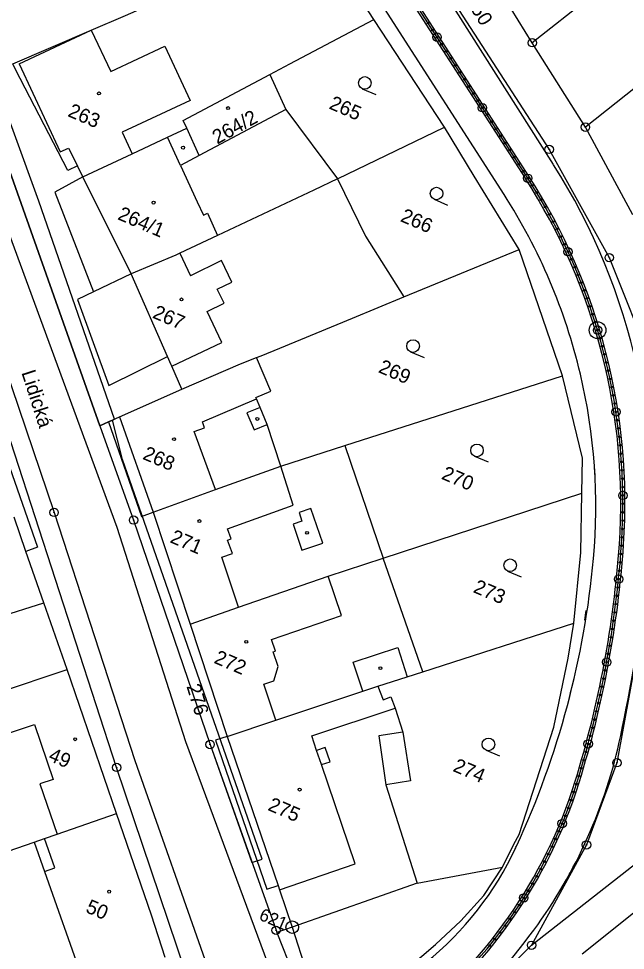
# Model space of a CAD drawing. Extents: x -548552 to -543113, y -1131925 to -1123599.
# Drawn here: x -548049 to -547976.7, y -1130669.2 to -1130558.1 of the extents above; entities that cross this region are included whole.
import ezdxf

# ---------------------------------------------------------------- set-up
doc = ezdxf.new("R2010")
doc.units = 0
for name, color, linetype in [('Hranice parcel', 7, 'Continuous'), ('Parcelní čísla', 7, 'Continuous'), ('Pop  PČ popisy', 7, 'Continuous'), ('PROFILY NÁVRH', 7, 'Continuous'), ('STANIČENÍ', 7, 'Continuous'), ('Vnitřní kresba', 7, 'Continuous'), ('Věcná břemena k části', 7, 'Continuous'), ('Značky bodu BP', 7, 'Continuous'), ('Značky budov', 7, 'Continuous'), ('Značky kultur', 7, 'Continuous')]:
    doc.layers.add(name, color=color, linetype=linetype)

msp = doc.modelspace()

# ---------------------------------------------------------------- linework, layer by layer
at = {"layer": 'Hranice parcel'}
for p, q in [((-547925.24, -1130511.69), (-547987.79, -1130560.98)), ((-547921.06, -1130523.02), (-547981.46, -1130571.05)), ((-548006.7, -1130558.22), (-548013.84, -1130547.08)), ((-547987.79, -1130560.98), (-547994.18, -1130550.73)), ((-547998.28, -1130571.06), (-548006.7, -1130558.22)), ((-548049.72, -1130563.51), (-548040.37, -1130559.48)), ((-547981.46, -1130571.05), (-547987.79, -1130560.98)), ((-548019.09, -1130564.77), (-548017.16, -1130568.93)), ((-548017.16, -1130568.93), (-548011.01, -1130577.22)), ((-548011.01, -1130577.22), (-547998.28, -1130571.06)), ((-547975.81, -1130581.5), (-547981.46, -1130571.05)), ((-548035.51, -1130574.21), (-548031.29, -1130572.24)), ((-548041.37, -1130576.96), (-548035.51, -1130574.21)), ((-548035.62, -1130588.52), (-548041.37, -1130576.96)), ((-548003.12, -1130591.29), (-547989.35, -1130585.62)), ((-547984.21, -1130600.71), (-547989.35, -1130585.62)), ((-548010.16, -1130609.02), (-547984.21, -1130600.71)), ((-548037, -1130605.6), (-548029.58, -1130602.3)), ((-548037, -1130605.6), (-548032.98, -1130616.96)), ((-548017.78, -1130611.46), (-548010.16, -1130609.02)), ((-548010.16, -1130609.02), (-548005.59, -1130622.46)), ((-548005.59, -1130622.46), (-547981.89, -1130614.69)), ((-548032.98, -1130616.96), (-548028.57, -1130630.3)), ((-548000.83, -1130635.98), (-548005.59, -1130622.46)), ((-548028.57, -1130630.3), (-548024.17, -1130643.69)), ((-548000.83, -1130635.98), (-547982.83, -1130630.21)), ((-548053.37, -1130639.11), (-548043.27, -1130635.7)), ((-548037.36, -1130652.87), (-548043.27, -1130635.7)), ((-547987.88, -1130668.6), (-547967.94, -1130652.95)), ((-547965.22, -1130656.32), (-547981.83, -1130669.68)), ((-548016.41, -1130666.44), (-548012.24, -1130679.44)), ((-547987.88, -1130668.6), (-548006.97, -1130687.25))]:
    msp.add_line(p, q, dxfattribs=at)
for points in [[(-548041.48, -1130484.13), (-548021.99, -1130517.74), (-547985.78, -1130573.7), (-547978.62, -1130586.61), (-547973.44, -1130599.62), (-547973.28, -1130611.12), (-547973.7, -1130624.88), (-547977.7, -1130646.84), (-547981.33, -1130656.63), (-547987.88, -1130668.6)], [(-548039.34, -1130606.65), (-548051.27, -1130573.08), (-548067.49, -1130533.25), (-548072.39, -1130522.4)], [(-548024.97, -1130684.14), (-548037.35, -1130647.39), (-548054.37, -1130595.1), (-548067.35, -1130560.8), (-548076.02, -1130541.68), (-548076.18, -1130541.3)], [(-548040.37, -1130559.48), (-548036.3, -1130557.72), (-548033.4, -1130556.48)], [(-548019.09, -1130564.77), (-548016.71, -1130563.5), (-548006.7, -1130558.22)], [(-548040.37, -1130559.48), (-548038.05, -1130564.43), (-548031.61, -1130561.41), (-548028.58, -1130567.87), (-548036.7, -1130571.66), (-548035.51, -1130574.21)], [(-548041.37, -1130576.96), (-548042.02, -1130575.66), (-548043.16, -1130576.23), (-548049.43, -1130564.18), (-548049.72, -1130563.51)], [(-548031.29, -1130572.24), (-548028.98, -1130571.16), (-548029.41, -1130570.24), (-548019.09, -1130564.77)], [(-548017.16, -1130568.93), (-548027.51, -1130574.43), (-548029.74, -1130575.61), (-548031.29, -1130572.24)], [(-547989.35, -1130585.62), (-547994.71, -1130576.89), (-547998.28, -1130571.06)], [(-548011.01, -1130577.22), (-548013.86, -1130578.56), (-548025.33, -1130583.96), (-548029.81, -1130586.08), (-548030.31, -1130586.31), (-548035.62, -1130588.52)], [(-548011.01, -1130577.22), (-548007.69, -1130584.04), (-548003.12, -1130591.29)], [(-548029.58, -1130602.3), (-548030.77, -1130599.56), (-548030.85, -1130599.39), (-548031.29, -1130598.38), (-548035.62, -1130588.52)], [(-548020.67, -1130598.52), (-548020.14, -1130598.3), (-548017.91, -1130597.4), (-548009.22, -1130593.81), (-548003.12, -1130591.29)], [(-548029.58, -1130602.3), (-548022.57, -1130599.28), (-548020.67, -1130598.52)], [(-548017.78, -1130611.46), (-548019.39, -1130606.5), (-548020.24, -1130604.46), (-548020.68, -1130603.46), (-548020.76, -1130603.27), (-548018.97, -1130602.52), (-548020.67, -1130598.52)], [(-547981.89, -1130614.69), (-547981.79, -1130610.5), (-547984.21, -1130600.71)], [(-548039.34, -1130606.65), (-548038.34, -1130606.19), (-548037, -1130605.6)], [(-548039.34, -1130606.65), (-548035.33, -1130617.91), (-548026.21, -1130644.66), (-548018.35, -1130666.82), (-548018.26, -1130667.08), (-548016.3, -1130672.01), (-548012.24, -1130679.44)], [(-548032.98, -1130616.96), (-548025.57, -1130614.27), (-548017.78, -1130611.46)], [(-547982.83, -1130630.21), (-547981.99, -1130621.77), (-547981.89, -1130614.69)], [(-548043.27, -1130635.7), (-548046.02, -1130627.78), (-548048.17, -1130621.63), (-548049.59, -1130617.56)], [(-548028.57, -1130630.3), (-548022.82, -1130628.3), (-548012.14, -1130624.6), (-548005.59, -1130622.46)], [(-548012.24, -1130679.44), (-548002.6, -1130671.28), (-547999.34, -1130668.52), (-547996.3, -1130665.69), (-547993.59, -1130662.67), (-547991.35, -1130659.28), (-547989.98, -1130656.53), (-547989.37, -1130655.41), (-547985.23, -1130642.61), (-547983.5, -1130634.36), (-547982.83, -1130630.21)], [(-548006.2, -1130637.71), (-548002.73, -1130636.59), (-548000.83, -1130635.98)], [(-548024.17, -1130643.69), (-548018.38, -1130641.77), (-548008.01, -1130638.31), (-548006.2, -1130637.71)], [(-548006.2, -1130637.71), (-548005.58, -1130639.33), (-548004.65, -1130638.97), (-548004.13, -1130640.33), (-548003.22, -1130643.18), (-548002.3, -1130649.01), (-548005.26, -1130649.48), (-548001.53, -1130661.2), (-548016.41, -1130666.44)], [(-548024.17, -1130643.69), (-548018.11, -1130661.46), (-548017.93, -1130662.01), (-548016.41, -1130666.44)], [(-548047.2, -1130656.29), (-548045.97, -1130655.87), (-548044.46, -1130655.34), (-548037.36, -1130652.87)], [(-548031.55, -1130670.08), (-548033.2, -1130665.02), (-548037.36, -1130652.87)], [(-548063.22, -1130661.62), (-548050.3, -1130657.38), (-548047.2, -1130656.29)], [(-548047.2, -1130656.29), (-548045.96, -1130659.81), (-548041.48, -1130672.53), (-548041.79, -1130672.64), (-548041.55, -1130673.37)]]:
    msp.add_lwpolyline(points, dxfattribs=at)
at = {"layer": 'PROFILY NÁVRH'}
msp.add_line((-547985.25, -1130575.52), (-547999.5, -1130553.08), dxfattribs=at)
for points in [[(-547988.2, -1130576.88), (-548019.2, -1130528.68), (-548034.37, -1130503.29)], [(-547988.62, -1130577.15), (-548019.63, -1130528.94), (-548034.8, -1130503.55)], [(-547991.16, -1130579.07), (-548005.43, -1130556.89)]]:
    msp.add_lwpolyline(points, dxfattribs=at)
for centre, radius, start, end in [((-548048.86, -1130615.89), 75.33, 352.3069, 32.4031), ((-548048.86, -1130615.89), 71.62, 356.0912, 32.7509), ((-548048.86, -1130615.89), 72.12, 356.0912, 32.7509), ((-548049.18, -1130616.39), 68.98, 13.3179, 32.7509), ((-548048.79, -1130616.3), 68.58, 354.8235, 13.3179), ((-548101.1, -1130612.32), 123.98, 342.7708, 356.0912), ((-548101.1, -1130612.32), 124.48, 342.7708, 356.0912), ((-548084.22, -1130613.09), 104.15, 335.2035, 354.8235), ((-548214.79, -1130593.48), 242.77, 348.0841, 352.3069), ((-548036.18, -1130631.17), 60.23, 323.7358, 348.0841), ((-548038.28, -1130631.81), 58.21, 307.0781, 342.7708), ((-548038.28, -1130631.81), 58.71, 307.0781, 342.7708), ((-548024.35, -1130640.88), 38.15, 308.652, 335.0978), ((-548051.88, -1130619.65), 79.7, 312.7399, 323.7358)]:
    msp.add_arc(centre, radius, start, end, dxfattribs=at)
at = {"layer": 'STANIČENÍ'}
msp.add_lwpolyline([(-547988.41, -1130577.01), (-548019.42, -1130528.81), (-548034.58, -1130503.42)], dxfattribs=at)
for centre, radius in [((-548000.23, -1130558.63), 0.1), ((-547999.69, -1130559.47), 0.1), ((-547999.15, -1130560.32), 0.5), ((-547999.15, -1130560.32), 0.1), ((-547998.61, -1130561.16), 0.1), ((-547998.07, -1130562), 0.1), ((-547997.53, -1130562.84), 0.1), ((-547996.99, -1130563.68), 0.1), ((-547996.44, -1130564.52), 0.1), ((-547995.9, -1130565.36), 0.1), ((-547995.36, -1130566.2), 0.1), ((-547994.82, -1130567.04), 0.1), ((-547994.28, -1130567.89), 0.1), ((-547993.74, -1130568.73), 0.5), ((-547993.74, -1130568.73), 0.1), ((-547993.2, -1130569.57), 0.1), ((-547992.66, -1130570.41), 0.1), ((-547992.12, -1130571.25), 0.1), ((-547991.58, -1130572.09), 0.1), ((-547991.03, -1130572.93), 0.1), ((-547990.49, -1130573.77), 0.1), ((-547989.95, -1130574.61), 0.1), ((-547989.41, -1130575.45), 0.1), ((-547988.87, -1130576.3), 0.1), ((-547988.33, -1130577.14), 0.5), ((-547988.33, -1130577.14), 0.1), ((-547987.8, -1130577.98), 0.1), ((-547987.27, -1130578.84), 0.1), ((-547986.77, -1130579.7), 0.1), ((-547986.27, -1130580.56), 0.1), ((-547985.78, -1130581.44), 0.1), ((-547985.31, -1130582.32), 0.1), ((-547984.85, -1130583.21), 0.1), ((-547984.4, -1130584.1), 0.1), ((-547983.96, -1130585), 0.1), ((-547983.54, -1130585.91), 0.5), ((-547983.54, -1130585.91), 0.1), ((-547983.13, -1130586.82), 0.1), ((-547982.73, -1130587.73), 0.1), ((-547982.35, -1130588.66), 0.1), ((-547981.97, -1130589.59), 0.1), ((-547981.61, -1130590.52), 0.1), ((-547981.27, -1130591.46), 0.1), ((-547980.93, -1130592.4), 0.1), ((-547980.93, -1130592.4), 0.1), ((-547980.61, -1130593.35), 0.1), ((-547980.61, -1130593.35), 0.1), ((-547980.01, -1130595.25), 1), ((-547980.31, -1130594.3), 0.1), ((-547980.31, -1130594.3), 0.1), ((-547980.01, -1130595.25), 0.5), ((-547980.01, -1130595.25), 0.5), ((-547980.01, -1130595.25), 0.1), ((-547980.01, -1130595.25), 0.1), ((-547979.73, -1130596.21), 0.1), ((-547979.73, -1130596.21), 0.1), ((-547979.46, -1130597.18), 0.1), ((-547979.46, -1130597.18), 0.1), ((-547979.21, -1130598.14), 0.1), ((-547979.21, -1130598.14), 0.1), ((-547978.97, -1130599.12), 0.1), ((-547978.97, -1130599.12), 0.1), ((-547978.74, -1130600.09), 0.1), ((-547978.74, -1130600.09), 0.1), ((-547978.53, -1130601.07), 0.1), ((-547978.53, -1130601.07), 0.1), ((-547978.33, -1130602.05), 0.1), ((-547978.15, -1130603.03), 0.1), ((-547977.81, -1130605), 0.5), ((-547977.97, -1130604.01), 0.1), ((-547977.81, -1130605), 0.1), ((-547977.67, -1130605.99), 0.1), ((-547977.54, -1130606.98), 0.1), ((-547977.42, -1130607.98), 0.1), ((-547977.32, -1130608.97), 0.1), ((-547977.23, -1130609.97), 0.1), ((-547977.15, -1130610.96), 0.1), ((-547977.09, -1130611.96), 0.1), ((-547977.04, -1130612.96), 0.1), ((-547976.99, -1130614.96), 0.5), ((-547977.01, -1130613.96), 0.1), ((-547976.99, -1130614.96), 0.1), ((-547976.98, -1130615.96), 0.1), ((-547977.01, -1130617.96), 0.1), ((-547976.99, -1130616.96), 0.1), ((-547977.05, -1130618.96), 0.1), ((-547977.1, -1130619.96), 0.1), ((-547977.16, -1130620.96), 0.1), ((-547977.24, -1130621.95), 0.1), ((-547977.32, -1130622.95), 0.1), ((-547977.51, -1130624.94), 0.5), ((-547977.41, -1130623.95), 0.1), ((-547977.51, -1130624.94), 0.1), ((-547977.72, -1130626.93), 0.1), ((-547977.61, -1130625.93), 0.1), ((-547977.85, -1130627.92), 0.1), ((-547977.98, -1130628.91), 0.1), ((-547978.11, -1130629.9), 0.1), ((-547978.26, -1130630.89), 0.1), ((-547978.41, -1130631.88), 0.1), ((-547978.57, -1130632.87), 0.1), ((-547978.92, -1130634.84), 0.5), ((-547978.74, -1130633.85), 0.1), ((-547979.11, -1130635.82), 0.1), ((-547978.92, -1130634.84), 0.1), ((-547979.3, -1130636.8), 0.1), ((-547979.5, -1130637.78), 0.1), ((-547979.71, -1130638.76), 0.1), ((-547979.92, -1130639.73), 0.1), ((-547980.15, -1130640.71), 0.1), ((-547980.38, -1130641.68), 0.1), ((-547980.62, -1130642.65), 0.1), ((-547981.13, -1130644.59), 0.5), ((-547981.13, -1130644.59), 0.1), ((-547980.87, -1130643.62), 0.1), ((-547981.39, -1130645.55), 0.1), ((-547981.66, -1130646.52), 0.1), ((-547981.94, -1130647.48), 0.1), ((-547982.23, -1130648.43), 0.1), ((-547982.52, -1130649.39), 0.1), ((-547983.16, -1130651.29), 0.1), ((-547982.83, -1130650.34), 0.1), ((-547983.5, -1130652.23), 0.1), ((-547983.85, -1130653.16), 0.1), ((-547984.23, -1130654.09), 0.5), ((-547984.23, -1130654.09), 0.1), ((-547984.62, -1130655.01), 0.1), ((-547985.44, -1130656.83), 0.1), ((-547985.02, -1130655.92), 0.1), ((-547985.88, -1130657.73), 0.1), ((-547986.33, -1130658.62), 0.1), ((-547986.79, -1130659.51), 0.1), ((-547987.77, -1130661.25), 0.1), ((-547987.28, -1130660.38), 0.1), ((-547988.28, -1130662.11), 0.1), ((-547988.81, -1130662.96), 0.5), ((-547988.81, -1130662.96), 0.1), ((-547989.9, -1130664.64), 0.1), ((-547989.35, -1130663.8), 0.1), ((-547990.47, -1130665.46), 0.1), ((-547991.05, -1130666.27), 0.1), ((-547992.26, -1130667.87), 0.1), ((-547991.65, -1130667.07), 0.1), ((-547992.88, -1130668.65), 0.1)]:
    msp.add_circle(centre, radius, dxfattribs=at)
for centre, radius, start, end in [((-548048.86, -1130615.89), 71.87, 356.0912, 32.7509), ((-548048.86, -1130615.89), 68.5, 24.3361, 25.5975), ((-548048.86, -1130615.89), 68.63, 2.1837, 3.4931), ((-548101.1, -1130612.32), 124.23, 342.7708, 356.0912), ((-548101.1, -1130612.32), 120.84, 351.6682, 352.2207), ((-548101.1, -1130612.32), 120.74, 347.0975, 347.6389), ((-548038.28, -1130631.81), 58.46, 307.0781, 342.7708), ((-548038.28, -1130631.81), 54.64, 332.4655, 333.1658), ((-548038.28, -1130631.81), 61.78, 332.5857, 332.9808)]:
    msp.add_arc(centre, radius, start, end, dxfattribs=at)
at = {"layer": 'Vnitřní kresba'}
for p, q in [((-548048.99, -1130563.51), (-548040.37, -1130559.48)), ((-548048.99, -1130563.51), (-548044.09, -1130573.99)), ((-548027.51, -1130574.43), (-548028.98, -1130571.16)), ((-548053.79, -1130574.03), (-548037.32, -1130618.76)), ((-548044.09, -1130573.99), (-548043.08, -1130573.54)), ((-548043.08, -1130573.54), (-548042.02, -1130575.66)), ((-548041.37, -1130576.96), (-548044.73, -1130578.78)), ((-548044.73, -1130578.78), (-548040.13, -1130590.67)), ((-548029.81, -1130586.08), (-548028.55, -1130588.76)), ((-548024.86, -1130586.96), (-548028.55, -1130588.76)), ((-548023.6, -1130589.54), (-548024.86, -1130586.96)), ((-548035.62, -1130588.52), (-548040.13, -1130590.67)), ((-548025.35, -1130590.38), (-548023.6, -1130589.54)), ((-548040.13, -1130590.67), (-548042.03, -1130591.58)), ((-548024.53, -1130592.02), (-548025.35, -1130590.38)), ((-548042.03, -1130591.58), (-548038.28, -1130601.87)), ((-548026.57, -1130593.01), (-548024.53, -1130592.02)), ((-548024.83, -1130596.74), (-548026.57, -1130593.01)), ((-548052.48, -1130594.39), (-548044.81, -1130616.99)), ((-548030.77, -1130599.56), (-548024.83, -1130596.74)), ((-548038.28, -1130601.87), (-548031.29, -1130598.38)), ((-548027.1, -1130606.19), (-548020.68, -1130603.46)), ((-548020.24, -1130604.46), (-548021.81, -1130605.11)), ((-548021.81, -1130605.11), (-548020.96, -1130607.14)), ((-548038.34, -1130606.19), (-548034.38, -1130617.46)), ((-548026.86, -1130606.9), (-548027.1, -1130606.19)), ((-548020.96, -1130607.14), (-548019.39, -1130606.5)), ((-548028.09, -1130607.32), (-548026.86, -1130606.9)), ((-548025.57, -1130614.27), (-548028.09, -1130607.32)), ((-548051.34, -1130608.15), (-548046.77, -1130621.14)), ((-548016.3, -1130616.13), (-548017.78, -1130611.46)), ((-548024.13, -1130618.96), (-548016.3, -1130616.13)), ((-548014.19, -1130616.51), (-548015.6, -1130616.99)), ((-548012.78, -1130620.66), (-548014.19, -1130616.51)), ((-548044.81, -1130616.99), (-548035.2, -1130646.58)), ((-548034.38, -1130617.46), (-548032.98, -1130616.96)), ((-548015.6, -1130616.99), (-548015.26, -1130618.02)), ((-548037.32, -1130618.76), (-548029.14, -1130644.29)), ((-548023.69, -1130620.15), (-548024.13, -1130618.96)), ((-548015.26, -1130618.02), (-548016.32, -1130618.37)), ((-548016.32, -1130618.37), (-548015.26, -1130621.5)), ((-548024.12, -1130620.3), (-548023.69, -1130620.15)), ((-548046.77, -1130621.14), (-548048.17, -1130621.63)), ((-548023.55, -1130621.87), (-548024.12, -1130620.3)), ((-548015.26, -1130621.5), (-548012.78, -1130620.66)), ((-548024.8, -1130622.33), (-548023.55, -1130621.87)), ((-548022.82, -1130628.3), (-548024.8, -1130622.33)), ((-548010.54, -1130629.27), (-548012.14, -1130624.6)), ((-548054.82, -1130630.55), (-548046.02, -1130627.78)), ((-548018.9, -1130632.16), (-548010.54, -1130629.27)), ((-548018.42, -1130633.52), (-548018.9, -1130632.16)), ((-548009.16, -1130634.84), (-548003.84, -1130633.11)), ((-548003.84, -1130633.11), (-548002.73, -1130636.59)), ((-548018.7, -1130633.61), (-548018.42, -1130633.52)), ((-548018.1, -1130635.37), (-548018.7, -1130633.61)), ((-548018.61, -1130637.07), (-548018.1, -1130635.37)), ((-548008.01, -1130638.31), (-548009.16, -1130634.84)), ((-548019.8, -1130637.46), (-548018.61, -1130637.07)), ((-548018.38, -1130641.77), (-548019.8, -1130637.46)), ((-548014.09, -1130643.64), (-548004.13, -1130640.33)), ((-548061.68, -1130647.13), (-548047.16, -1130642.29)), ((-548047.16, -1130642.29), (-548044.93, -1130648.82)), ((-548003.22, -1130643.18), (-548006.08, -1130643.63)), ((-548029.14, -1130644.29), (-548018.55, -1130672.86)), ((-548024.17, -1130643.69), (-548025.55, -1130644.16)), ((-548025.55, -1130644.16), (-548019.45, -1130661.93)), ((-548013.51, -1130645.36), (-548014.09, -1130643.64)), ((-548006.08, -1130643.63), (-548005.26, -1130649.48)), ((-548012.48, -1130645.01), (-548013.51, -1130645.36)), ((-548012.93, -1130647.06), (-548013.51, -1130645.36)), ((-548011.89, -1130646.71), (-548012.48, -1130645.01)), ((-548035.2, -1130646.58), (-548020.88, -1130687.16)), ((-548012.93, -1130647.06), (-548011.89, -1130646.71)), ((-548008.93, -1130658.9), (-548012.93, -1130647.06)), ((-548044.93, -1130648.82), (-548046.5, -1130649.35)), ((-548046.5, -1130649.35), (-548044.46, -1130655.34)), ((-548044.74, -1130659.38), (-548045.97, -1130655.87)), ((-548017.93, -1130662.01), (-548008.93, -1130658.9)), ((-548045.96, -1130659.81), (-548044.74, -1130659.38)), ((-548001.53, -1130661.2), (-547991.35, -1130659.28)), ((-548019.45, -1130661.93), (-548018.11, -1130661.46)), ((-548016.41, -1130666.44), (-548018.26, -1130667.08))]:
    msp.add_line(p, q, dxfattribs=at)
msp.add_lwpolyline([(-548029.74, -1130575.61), (-548027.74, -1130579.95), (-548027, -1130581.54), (-548026.5, -1130581.31), (-548025.33, -1130583.96)], dxfattribs=at)
at = {"layer": 'Věcná břemena k části'}
msp.add_lwpolyline([(-548072.39, -1130522.4), (-548071.31, -1130524.8), (-548070.52, -1130525.83), (-548069.21, -1130529.43), (-548067.49, -1130533.25), (-548051.27, -1130573.08), (-548039.34, -1130606.65), (-548038.34, -1130606.19), (-548037.86, -1130605.99), (-548037.61, -1130605.87), (-548046.61, -1130579.87), (-548066.97, -1130523.89), (-548071.5, -1130517.93)], dxfattribs=at)
msp.add_lwpolyline([(-548039.34, -1130606.65), (-548035.33, -1130617.91), (-548026.21, -1130644.66), (-548021.22, -1130658.72), (-548020.01, -1130658.34), (-548036.66, -1130610.67), (-548037.86, -1130605.99), (-548038.34, -1130606.19)], close=True, dxfattribs=at)
msp.add_lwpolyline([(-548039.34, -1130606.65), (-548035.33, -1130617.91), (-548026.21, -1130644.66), (-548021.22, -1130658.72), (-548020.01, -1130658.34), (-548036.66, -1130610.67), (-548037.86, -1130605.99), (-548038.34, -1130606.19)], close=True, dxfattribs=at)
at = {"layer": 'Značky bodu BP'}
for centre, radius in [((-547987.79, -1130560.98), 0.5), ((-547987.79, -1130560.98), 0.0303), ((-547981.46, -1130571.05), 0.5), ((-547981.46, -1130571.05), 0.0303), ((-547985.78, -1130573.7), 0.5), ((-547985.78, -1130573.7), 0.0303), ((-547978.62, -1130586.61), 0.5), ((-547978.62, -1130586.61), 0.0303), ((-548044.81, -1130616.99), 0.5), ((-548044.81, -1130616.99), 0.0303), ((-548035.33, -1130617.9), 0.5), ((-548035.33, -1130617.9), 0.0303), ((-548026.21, -1130644.66), 0.5), ((-548026.21, -1130644.66), 0.0303), ((-547977.7, -1130646.84), 0.5), ((-547977.7, -1130646.84), 0.0303), ((-548037.35, -1130647.39), 0.5), ((-548037.35, -1130647.39), 0.0303), ((-547981.33, -1130656.63), 0.5), ((-547981.33, -1130656.63), 0.0303), ((-548016.41, -1130666.44), 0.75), ((-548018.35, -1130666.82), 0.5), ((-548018.35, -1130666.82), 0.0303), ((-548016.41, -1130666.44), 0.03), ((-547987.88, -1130668.6), 0.5), ((-547987.88, -1130668.6), 0.0303)]:
    msp.add_circle(centre, radius, dxfattribs=at)
at = {"layer": 'Značky budov'}
for centre in [(-548039.46, -1130567.02), (-548024.06, -1130568.77), (-548029.44, -1130573.49), (-548032.95, -1130580.05), (-548029.62, -1130591.59), (-548020.58, -1130605.84), (-548030.51, -1130608.25), (-548027.48, -1130618.02), (-548014.65, -1130619.42), (-548021.9, -1130632.42), (-548005.9, -1130635.56), (-548042.3, -1130644.04), (-548015.53, -1130650.04), (-548038.24, -1130662.21)]:
    msp.add_circle(centre, 0.175, dxfattribs=at)
at = {"layer": 'Značky kultur'}
for p, q in [((-548008.06, -1130566.46), (-548006.45, -1130567.15)), ((-547999.5, -1130579.65), (-547997.89, -1130580.34)), ((-548002.3, -1130597.84), (-548000.69, -1130598.53)), ((-547994.68, -1130610.28), (-547993.07, -1130610.97)), ((-547990.73, -1130623.98), (-547989.12, -1130624.67)), ((-547993.31, -1130645.34), (-547991.7, -1130646.03))]:
    msp.add_line(p, q, dxfattribs=at)
for centre in [(-548007.76, -1130565.77), (-547999.21, -1130578.96), (-548002.01, -1130597.15), (-547994.39, -1130609.59), (-547990.43, -1130623.29), (-547993.02, -1130644.65)]:
    msp.add_circle(centre, 0.75, dxfattribs=at)

# ---------------------------------------------------------------- texts
at = {"layer": 'Parcelní čísla'}
for s, rotation, p in [('650', 301.8058, (-547995.85, -1130555.88)), ('265', 336.8058, (-548012.13, -1130568.8)), ('263', 336.8058, (-548043.28, -1130569.71)), ('264/2', 28.8058, (-548025.36, -1130573.13)), ('264/1', 336.8058, (-548037.34, -1130582)), ('266', 336.8058, (-548003.63, -1130582.23)), ('267', 336.8058, (-548033.18, -1130593.74)), ('269', 336.8058, (-548006.25, -1130600.24)), ('268', 336.8058, (-548034.36, -1130610.58)), ('270', 336.8058, (-547998.73, -1130612.95)), ('271', 336.8058, (-548031.09, -1130620.52)), ('273', 336.8058, (-547994.94, -1130626.47)), ('272', 336.8058, (-548025.85, -1130634.9)), ('276', 286.8058, (-548029.04, -1130637.71)), ('49', 336.8058, (-548045.6, -1130646.53)), ('274', 336.8058, (-547997.36, -1130647.8)), ('275', 336.8058, (-548019.43, -1130652.45)), ('50', 336.8058, (-548041.15, -1130664.62))]:
    msp.add_text(s, height=1.7, rotation=rotation, dxfattribs=at).set_placement(p)
at = {"layer": 'Pop  PČ popisy'}
msp.add_text('Lidická', height=1.7, rotation=287.8058, dxfattribs=at).set_placement((-548048.72, -1130600.31))
at = {"layer": 'Značky bodu BP'}
msp.add_text('621', height=1.5, rotation=336.8058, dxfattribs=at).set_placement((-548020.48, -1130665.51))

doc.saveas('drawing.dxf')
